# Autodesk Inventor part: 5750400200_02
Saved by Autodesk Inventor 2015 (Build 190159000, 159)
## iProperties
Created: 2020-07
Part Number: 5750400200_02
Checked By: TraceParts S.A.
Material: Generic
Catalog Web Link: www.traceparts.com
Document SubType Name: Modeling
Designer: TraceParts
Density: 1 g/cm^3
Appearance: Default
Company: TraceParts S.A.
Author: TraceParts
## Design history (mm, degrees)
feature "5750400200_02.ipt"
body "Solid1"
